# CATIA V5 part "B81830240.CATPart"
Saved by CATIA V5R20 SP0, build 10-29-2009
Part number: B81830240
Revision: 4
Definition: design
Nomenclature: B81830240
Source: made
Description: NOT SPECIFIED
Bounding box of the stored display mesh (mm): x -17.817 to 17.817, y -18 to 18, z 0 to 240
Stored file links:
  C:\Users\Raffaele\Desktop\3D X SITO CF\BOLEX\6-PILLAR REF 818\B81830240.CATPart
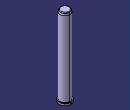
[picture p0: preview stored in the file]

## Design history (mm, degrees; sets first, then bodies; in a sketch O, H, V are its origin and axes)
Body1 "MANIFOLD_SOLID_BREP #370" (main body)
  Solid1: solid without history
